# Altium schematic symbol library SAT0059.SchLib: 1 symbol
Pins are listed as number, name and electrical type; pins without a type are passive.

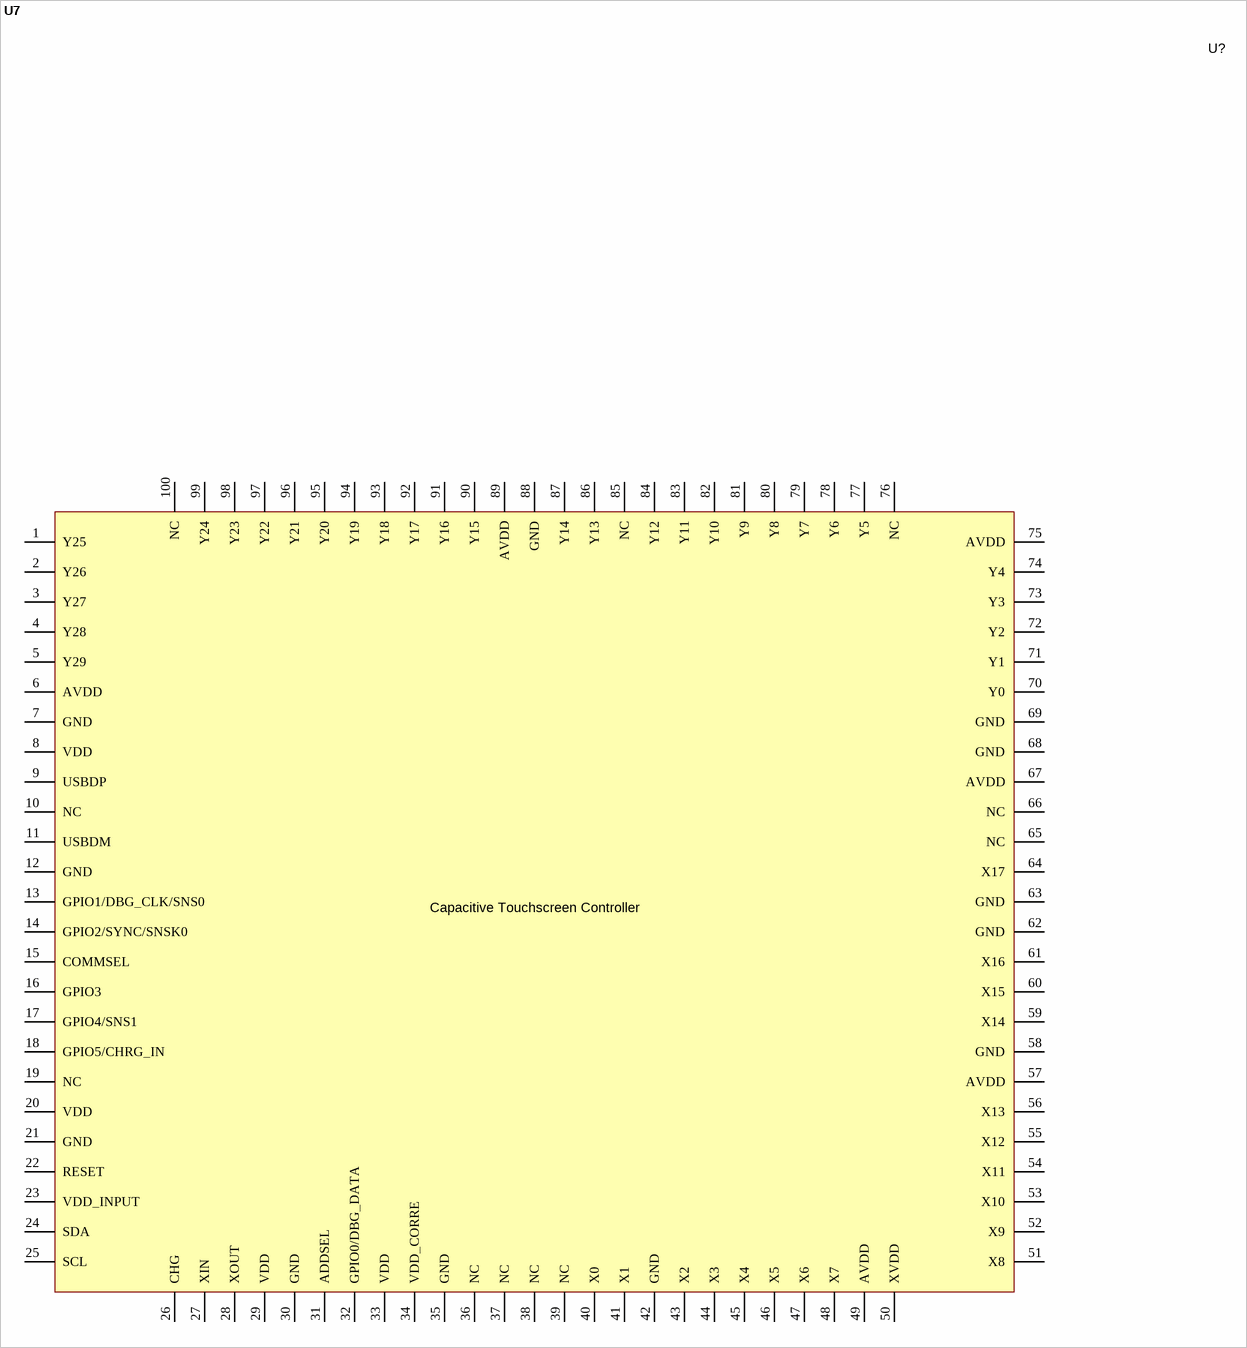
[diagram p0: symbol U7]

## U7
designator U?, comment Capacitive Touchscreen Controller
NDA Capacitive TouchScreen Controller
footprint U7 (100-pin QFP)
pins: 1 Y25, 2 Y26, 3 Y27, 4 Y28, 5 Y29, 6 AVDD, 7 GND, 8 VDD, 9 USBDP, 10 NC, 11 USBDM, 12 GND, 13 GPIO1/DBG_CLK/SNS0, 14 GPIO2/SYNC/SNSK0, 15 COMMSEL, 16 GPIO3, 17 GPIO4/SNS1, 18 GPIO5/CHRG_IN, 19 NC, 20 VDD, 21 GND, 22 RESET, 23 VDD_INPUT, 24 SDA, 25 SCL, 26 CHG, 27 XIN, 28 XOUT, 29 VDD, 30 GND, 31 ADDSEL, 32 GPIO0/DBG_DATA, 33 VDD, 34 VDD_CORRE, 35 GND, 36 NC, 37 NC, 38 NC, 39 NC, 40 X0, 41 X1, 42 GND, 43 X2, 44 X3, 45 X4, 46 X5, 47 X6, 48 X7, 49 AVDD, 50 XVDD, 51 X8, 52 X9, 53 X10, 54 X11, 55 X12, 56 X13, 57 AVDD, 58 GND, 59 X14, 60 X15, 61 X16, 62 GND, 63 GND, 64 X17, 65 NC, 66 NC, 67 AVDD, 68 GND, 69 GND, 70 Y0, 71 Y1, 72 Y2, 73 Y3, 74 Y4, 75 AVDD, 76 NC, 77 Y5, 78 Y6, 79 Y7, 80 Y8, 81 Y9, 82 Y10, 83 Y11, 84 Y12, 85 NC, 86 Y13, 87 Y14, 88 GND, 89 AVDD, 90 Y15, 91 Y16, 92 Y17, 93 Y18, 94 Y19, 95 Y20, 96 Y21, 97 Y22, 98 Y23, 99 Y24, 100 NC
